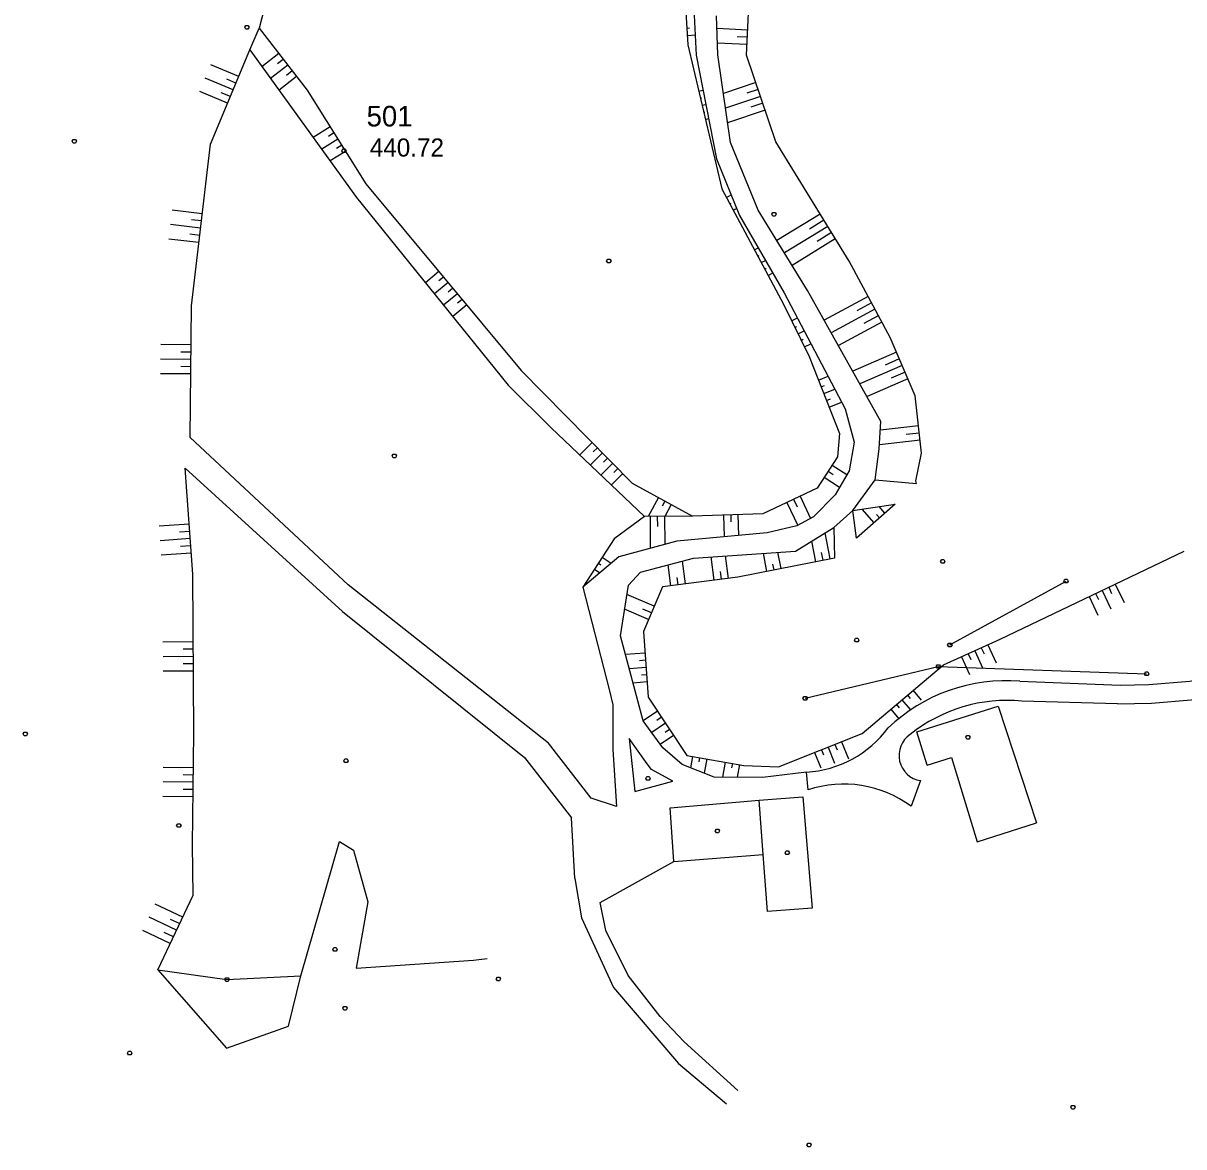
# Model space of a CAD drawing. Extents: x -664960 to -662754, y -993849 to -991145.
# Drawn here: x -664960.2 to -664768.3, y -993629.6 to -993443.9 of the extents above; entities that cross this region are included whole.
import ezdxf

# ---------------------------------------------------------------- set-up
doc = ezdxf.new("R2010")
doc.units = 0
for name, color, linetype in [('Vrstva 1', 7, 'Continuous'), ('Vrstva 11', 7, 'Continuous'), ('Vrstva 13', 7, 'Continuous'), ('Vrstva 18', 7, 'Continuous'), ('Vrstva 23', 7, 'Continuous'), ('Vrstva 27', 7, 'Continuous'), ('Vrstva 37', 7, 'Continuous'), ('Vrstva 57', 7, 'Continuous'), ('Vrstva 63', 7, 'Continuous'), ('Vrstva 8', 7, 'Continuous'), ('Vrstva 9', 7, 'Continuous')]:
    doc.layers.add(name, color=color, linetype=linetype)

msp = doc.modelspace()

# ---------------------------------------------------------------- linework, layer by layer
at = {"layer": 'Vrstva 11'}
for p, q in [((-664802.496, -993579.204), (-664792.708, -993576.061)), ((-664852.637, -993582.457), (-664837.866, -993581.285)), ((-664829.764, -993590.158), (-664837.168, -993590.719))]:
    msp.add_line(p, q, dxfattribs=at)
for points in [[(-664810.763, -993566.551), (-664812.455, -993561.016), (-664798.999, -993556.803), (-664792.708, -993576.061)], [(-664810.763, -993566.551), (-664806.76, -993565.249), (-664802.496, -993579.204)], [(-664837.168, -993590.719), (-664837.866, -993581.285), (-664838.53, -993572.31), (-664831.29, -993571.79), (-664829.764, -993590.158)], [(-664852.637, -993582.457), (-664853.24, -993573.56), (-664838.53, -993572.31)]]:
    msp.add_lwpolyline(points, dxfattribs=at)
at = {"layer": 'Vrstva 13'}
for points in [[(-664951.534, -993463.13), (-664951.354, -993463.43), (-664951.534, -993463.73), (-664951.894, -993463.73), (-664952.074, -993463.43), (-664951.894, -993463.13), (-664951.534, -993463.13)], [(-664835.885, -993475.193), (-664835.705, -993475.493), (-664835.885, -993475.793), (-664836.245, -993475.793), (-664836.425, -993475.493), (-664836.245, -993475.193), (-664835.885, -993475.193)], [(-664863.186, -993482.897), (-664863.006, -993483.197), (-664863.186, -993483.497), (-664863.546, -993483.497), (-664863.726, -993483.197), (-664863.546, -993482.897), (-664863.186, -993482.897)], [(-664898.628, -993515.117), (-664898.448, -993515.417), (-664898.628, -993515.717), (-664898.988, -993515.717), (-664899.168, -993515.417), (-664898.988, -993515.117), (-664898.628, -993515.117)], [(-664822.219, -993545.565), (-664822.039, -993545.865), (-664822.219, -993546.165), (-664822.579, -993546.165), (-664822.759, -993545.865), (-664822.579, -993545.565), (-664822.219, -993545.565)], [(-664959.61, -993561.068), (-664959.43, -993561.368), (-664959.61, -993561.668), (-664959.97, -993561.668), (-664960.15, -993561.368), (-664959.97, -993561.068), (-664959.61, -993561.068)], [(-664906.634, -993565.503), (-664906.454, -993565.803), (-664906.634, -993566.103), (-664906.994, -993566.103), (-664907.174, -993565.803), (-664906.994, -993565.503), (-664906.634, -993565.503)], [(-664908.433, -993596.677), (-664908.253, -993596.977), (-664908.433, -993597.277), (-664908.793, -993597.277), (-664908.973, -993596.977), (-664908.793, -993596.677), (-664908.433, -993596.677)]]:
    msp.add_lwpolyline(points, dxfattribs=at)
at = {"layer": 'Vrstva 18'}
for points in [[(-664923.01, -993444.3), (-664922.83, -993444.6), (-664923.01, -993444.9), (-664923.37, -993444.9), (-664923.55, -993444.6), (-664923.37, -993444.3), (-664923.01, -993444.3)], [(-664934.25, -993576.2), (-664934.07, -993576.5), (-664934.25, -993576.8), (-664934.61, -993576.8), (-664934.79, -993576.5), (-664934.61, -993576.2), (-664934.25, -993576.2)], [(-664881.433, -993601.55), (-664881.253, -993601.85), (-664881.433, -993602.15), (-664881.793, -993602.15), (-664881.973, -993601.85), (-664881.793, -993601.55), (-664881.433, -993601.55)], [(-664906.79, -993606.41), (-664906.61, -993606.71), (-664906.79, -993607.01), (-664907.15, -993607.01), (-664907.33, -993606.71), (-664907.15, -993606.41), (-664906.79, -993606.41)], [(-664942.38, -993613.82), (-664942.2, -993614.12), (-664942.38, -993614.42), (-664942.74, -993614.42), (-664942.92, -993614.12), (-664942.74, -993613.82), (-664942.38, -993613.82)], [(-664786.468, -993622.755), (-664786.288, -993623.055), (-664786.468, -993623.355), (-664786.828, -993623.355), (-664787.008, -993623.055), (-664786.828, -993622.755), (-664786.468, -993622.755)], [(-664830.086, -993628.994), (-664829.906, -993629.294), (-664830.086, -993629.594), (-664830.446, -993629.594), (-664830.626, -993629.294), (-664830.446, -993628.994), (-664830.086, -993628.994)]]:
    msp.add_lwpolyline(points, dxfattribs=at)
at = {"layer": 'Vrstva 23'}
for p, q in [((-664795.421, -993552.658), (-664778.865, -993553.318)), ((-664779.297, -993556.373), (-664795.089, -993555.953)), ((-664830.44, -993570.63), (-664830.71, -993567.69)), ((-664811.85, -993569.09), (-664813.41, -993573.33))]:
    msp.add_line(p, q, dxfattribs=at)
for points in [[(-664778.865, -993553.318), (-664774.13, -993553.174), (-664767.338, -993552.644), (-664762.115, -993551.613)], [(-664779.297, -993556.373), (-664773.686, -993556.3), (-664767.101, -993555.71), (-664761.262, -993554.563)]]:
    msp.add_lwpolyline(points, dxfattribs=at)
for centre, radius, start, end in [((-664797.685, -993580.909), 28.342, 85.41758, 133.50928), ((-664797.554, -993581.435), 25.601, 84.47369, 128.66666), ((-664831.789, -993549.591), 18.131, 273.41191, 323.58536), ((-664811.201, -993564.935), 4.206, 123.95198, 261.12469), ((-664824.509, -993588.276), 18.616, 53.40247, 108.57972)]:
    msp.add_arc(centre, radius, start, end, dxfattribs=at)
at = {"layer": 'Vrstva 27'}
for p, q in [((-664868.995, -993585.253), (-664869.51, -993575.25)), ((-664864.802, -993589.247), (-664852.637, -993582.457))]:
    msp.add_line(p, q, dxfattribs=at)
for points in [[(-664849.24, -993442.58), (-664848.96, -993449.22), (-664845.6, -993466.32), (-664841.78, -993475.72), (-664834.37, -993488.49), (-664824.32, -993507.62), (-664822.82, -993513.13), (-664823.66, -993517.88), (-664825.98, -993521.88), (-664829.54, -993525.5), (-664832.27, -993526.99), (-664837.19, -993528.16), (-664852.12, -993529.5), (-664861.73, -993532.08), (-664867.68, -993537.12), (-664863.27, -993554.24), (-664862.7, -993556.56), (-664862.7, -993563.93)], [(-664830.71, -993567.69), (-664837.96, -993568.55), (-664845.98, -993568.5), (-664851.25, -993566.43), (-664854.46, -993563.69), (-664857.68, -993559.18), (-664861.44, -993545.16), (-664860.14, -993536.81), (-664858.11, -993534.64), (-664849.37, -993532.3), (-664832.51, -993531.15), (-664826.16, -993527.24), (-664823.02, -993524.47), (-664819.37, -993519.36), (-664818.69, -993514.28), (-664818.39, -993509.72), (-664830.53, -993488.08), (-664838.71, -993474.83), (-664843.26, -993463.66), (-664845.33, -993449.14), (-664845.56, -993442.68)], [(-664862.7, -993563.93), (-664862.1, -993573.36), (-664866.27, -993571.96), (-664873.33, -993562.89), (-664906.44, -993536.75), (-664932.56, -993512.4)], [(-664933.37, -993517.43), (-664907.41, -993541.16), (-664877.3, -993565.24), (-664869.51, -993575.25)], [(-664859.09, -993570.89), (-664852.77, -993569.15), (-664856.29, -993567.22), (-664857.02, -993566.29), (-664860.03, -993562.12), (-664859.09, -993570.89)], [(-664868.995, -993585.253), (-664867.883, -993591.761), (-664862.613, -993603.257)], [(-664842.027, -993620.315), (-664850.896, -993612.253), (-664854.891, -993608.062), (-664860.192, -993601.276), (-664863.867, -993593.843), (-664864.802, -993589.247)], [(-664862.613, -993603.257), (-664851.845, -993615.834), (-664843.931, -993622.494)]]:
    msp.add_lwpolyline(points, dxfattribs=at)
at = {"layer": 'Vrstva 37'}
for points in [[(-664808.74, -993549.927), (-664808.56, -993550.227), (-664808.74, -993550.527), (-664809.1, -993550.527), (-664809.28, -993550.227), (-664809.1, -993549.927), (-664808.74, -993549.927)], [(-664774.309, -993551.112), (-664774.129, -993551.412), (-664774.309, -993551.712), (-664774.669, -993551.712), (-664774.849, -993551.412), (-664774.669, -993551.112), (-664774.309, -993551.112)], [(-664830.74, -993555.18), (-664830.56, -993555.48), (-664830.74, -993555.78), (-664831.1, -993555.78), (-664831.28, -993555.48), (-664831.1, -993555.18), (-664830.74, -993555.18)]]:
    msp.add_lwpolyline(points, dxfattribs=at)
at = {"layer": 'Vrstva 57'}
msp.add_lwpolyline([(-664830.92, -993555.48), (-664808.92, -993550.227), (-664774.489, -993551.412)], dxfattribs=at)
at = {"layer": 'Vrstva 63'}
for p, q in [((-664850.473, -993444.739), (-664850.033, -993444.71)), ((-664840.428, -993445.053), (-664845.484, -993444.818)), ((-664850.393, -993445.936), (-664849.102, -993445.851)), ((-664840.539, -993447.45), (-664845.398, -993447.224)), ((-664840.483, -993446.251), (-664842.134, -993446.175)), ((-664917.894, -993448.947), (-664920.693, -993451.109)), ((-664924.523, -993452.717), (-664929.139, -993450.794)), ((-664916.427, -993450.846), (-664919.285, -993453.054)), ((-664917.161, -993449.896), (-664918.102, -993450.624)), ((-664925.446, -993454.932), (-664930.062, -993453.01)), ((-664924.985, -993453.824), (-664926.522, -993453.184)), ((-664914.959, -993452.745), (-664917.876, -993454.998)), ((-664915.693, -993451.795), (-664916.654, -993452.538)), ((-664848.499, -993455.136), (-664847.829, -993454.978)), ((-664839.088, -993453.733), (-664844.419, -993455.531)), ((-664838.704, -993454.87), (-664840.55, -993455.493)), ((-664926.369, -993457.148), (-664930.984, -993455.225)), ((-664925.907, -993456.04), (-664927.444, -993455.4)), ((-664848.225, -993456.304), (-664848.016, -993456.255)), ((-664838.321, -993456.007), (-664844.074, -993457.948)), ((-664847.951, -993457.472), (-664847.365, -993457.335)), ((-664847.677, -993458.641), (-664847.496, -993458.598)), ((-664837.554, -993458.282), (-664843.73, -993460.365)), ((-664837.937, -993457.144), (-664839.923, -993457.814)), ((-664847.403, -993459.809), (-664846.902, -993459.691)), ((-664909.434, -993461.035), (-664912.23, -993462.79)), ((-664908.796, -993462.052), (-664909.704, -993462.622)), ((-664908.158, -993463.068), (-664910.819, -993464.738)), ((-664907.52, -993464.084), (-664908.384, -993464.626)), ((-664906.882, -993465.101), (-664909.408, -993466.686)), ((-664843.945, -993472.717), (-664843.169, -993472.302)), ((-664843.377, -993473.775), (-664843.157, -993473.657)), ((-664930.549, -993475.41), (-664935.514, -993474.823)), ((-664842.81, -993474.833), (-664842.26, -993474.538)), ((-664828.457, -993475.451), (-664835.611, -993479.849)), ((-664930.831, -993477.793), (-664935.796, -993477.206)), ((-664930.69, -993476.602), (-664932.343, -993476.406)), ((-664827.2, -993477.495), (-664834.351, -993481.891)), ((-664827.829, -993476.473), (-664830.21, -993477.937)), ((-664931.113, -993480.177), (-664936.078, -993479.59)), ((-664930.972, -993478.985), (-664932.625, -993478.789)), ((-664825.943, -993479.54), (-664833.09, -993483.934)), ((-664826.572, -993478.518), (-664828.952, -993479.981)), ((-664839.305, -993481.37), (-664838.692, -993481.042)), ((-664838.738, -993482.428), (-664838.522, -993482.312)), ((-664838.17, -993483.485), (-664837.487, -993483.119)), ((-664891.461, -993484.949), (-664893.68, -993486.796)), ((-664837.603, -993484.543), (-664837.364, -993484.414)), ((-664837.036, -993485.6), (-664836.282, -993485.196)), ((-664889.926, -993486.793), (-664892.173, -993488.664)), ((-664890.693, -993485.871), (-664891.437, -993486.49)), ((-664889.158, -993487.715), (-664889.911, -993488.342)), ((-664888.39, -993488.637), (-664890.666, -993490.532)), ((-664887.622, -993489.56), (-664888.385, -993490.195)), ((-664820.531, -993489.083), (-664827.784, -993492.975)), ((-664886.854, -993490.482), (-664889.159, -993492.401)), ((-664819.396, -993491.198), (-664826.61, -993495.068)), ((-664819.964, -993490.141), (-664822.372, -993491.433)), ((-664833.152, -993493.095), (-664832.196, -993492.629)), ((-664818.262, -993493.313), (-664825.435, -993497.162)), ((-664818.829, -993492.256), (-664821.225, -993493.541)), ((-664832.627, -993494.174), (-664832.297, -993494.014)), ((-664832.101, -993495.253), (-664831.079, -993494.755)), ((-664932.412, -993497.083), (-664937.412, -993497.035)), ((-664831.575, -993496.332), (-664831.224, -993496.16)), ((-664831.05, -993497.41), (-664829.962, -993496.88)), ((-664932.424, -993498.283), (-664934.089, -993498.267)), ((-664815.841, -993498.285), (-664823.049, -993501.415)), ((-664932.435, -993499.483), (-664937.435, -993499.435)), ((-664932.447, -993500.683), (-664934.112, -993500.667)), ((-664814.885, -993500.486), (-664821.869, -993503.519)), ((-664815.363, -993499.385), (-664817.726, -993500.412)), ((-664932.459, -993501.883), (-664937.458, -993501.835)), ((-664828.73, -993502.894), (-664827.135, -993502.262)), ((-664813.929, -993502.687), (-664820.688, -993505.623)), ((-664814.407, -993501.587), (-664816.695, -993502.581)), ((-664828.287, -993504.01), (-664827.717, -993503.784)), ((-664827.845, -993505.125), (-664826.012, -993504.399)), ((-664827.403, -993506.241), (-664826.753, -993505.983)), ((-664826.96, -993507.356), (-664824.89, -993506.535)), ((-664812.171, -993510.451), (-664818.484, -993511.147)), ((-664812.039, -993511.643), (-664814.212, -993511.883)), ((-664866.096, -993513.227), (-664868.189, -993515.289)), ((-664865.254, -993514.081), (-664865.941, -993514.759)), ((-664811.908, -993512.836), (-664818.644, -993513.579)), ((-664864.411, -993514.936), (-664866.447, -993516.942)), ((-664863.569, -993515.791), (-664864.237, -993516.449)), ((-664862.727, -993516.645), (-664864.705, -993518.595)), ((-664861.042, -993518.355), (-664862.963, -993520.247)), ((-664861.885, -993517.5), (-664862.534, -993518.14)), ((-664827.101, -993517.936), (-664826.277, -993518.473)), ((-664826.446, -993516.931), (-664824.024, -993518.508)), ((-664827.756, -993518.942), (-664825.23, -993520.587)), ((-664831.77, -993522.078), (-664830.027, -993525.766)), ((-664855.157, -993522.306), (-664856.873, -993525.435)), ((-664854.105, -993522.883), (-664854.569, -993523.729)), ((-664853.053, -993523.459), (-664854.125, -993525.415)), ((-664833.94, -993523.103), (-664832.137, -993526.917)), ((-664832.855, -993522.591), (-664832.265, -993523.84)), ((-664817.73, -993524.879), (-664818.692, -993523.794)), ((-664856.555, -993525.433), (-664856.516, -993530.68)), ((-664855.355, -993525.424), (-664855.343, -993527.067)), ((-664854.155, -993525.415), (-664854.12, -993530.037)), ((-664844.426, -993525.208), (-664844.305, -993528.799)), ((-664843.226, -993525.168), (-664843.187, -993526.341)), ((-664842.027, -993525.128), (-664841.911, -993528.584)), ((-664819.525, -993526.471), (-664821.509, -993524.234)), ((-664818.627, -993525.675), (-664819.118, -993525.122)), ((-664932.72, -993526.696), (-664937.708, -993527.046)), ((-664932.636, -993527.893), (-664934.297, -993528.009)), ((-664932.552, -993529.09), (-664937.54, -993529.44)), ((-664829.149, -993532.91), (-664829.823, -993529.496)), ((-664826.794, -993532.445), (-664827.642, -993528.153)), ((-664932.384, -993531.484), (-664937.372, -993531.834)), ((-664932.468, -993530.287), (-664934.129, -993530.403)), ((-664837.235, -993534.507), (-664837.827, -993531.513)), ((-664834.881, -993534.042), (-664835.413, -993531.348)), ((-664827.972, -993532.678), (-664828.225, -993531.394)), ((-664865.097, -993533.162), (-664864.704, -993533.418)), ((-664864.442, -993532.157), (-664862.961, -993533.123)), ((-664853.102, -993536.899), (-664853.556, -993533.421)), ((-664850.722, -993536.589), (-664851.217, -993532.794)), ((-664845.958, -993535.968), (-664846.462, -993532.102)), ((-664843.578, -993535.658), (-664844.063, -993531.938)), ((-664836.058, -993534.275), (-664836.245, -993533.327)), ((-664865.753, -993534.167), (-664864.872, -993534.741)), ((-664851.912, -993536.744), (-664852.07, -993535.533)), ((-664844.768, -993535.813), (-664844.933, -993534.55)), ((-664807.01, -993546.65), (-664787.8, -993536.1)), ((-664780.762, -993537.129), (-664780.277, -993538.142)), ((-664779.679, -993536.611), (-664778.224, -993539.652)), ((-664855.866, -993540.271), (-664860.376, -993538.326)), ((-664784.009, -993538.684), (-664782.554, -993541.723)), ((-664782.927, -993538.166), (-664782.442, -993539.178)), ((-664781.844, -993537.648), (-664780.389, -993540.688)), ((-664856.817, -993542.475), (-664860.757, -993540.776)), ((-664856.342, -993541.373), (-664857.749, -993540.766)), ((-664932.059, -993546.176), (-664937.059, -993546.213)), ((-664801.811, -993547.121), (-664801.365, -993548.108)), ((-664800.717, -993546.626), (-664799.372, -993549.602)), ((-664932.041, -993548.576), (-664937.041, -993548.612)), ((-664932.05, -993547.376), (-664933.715, -993547.388)), ((-664857.394, -993547.995), (-664860.615, -993548.236)), ((-664805.091, -993548.604), (-664803.768, -993551.532)), ((-664803.998, -993548.109), (-664803.555, -993549.088)), ((-664802.904, -993547.615), (-664801.57, -993550.567)), ((-664932.024, -993550.976), (-664937.024, -993551.012)), ((-664932.033, -993549.776), (-664933.698, -993549.788)), ((-664857.215, -993550.388), (-664859.982, -993550.595)), ((-664857.305, -993549.192), (-664858.302, -993549.266)), ((-664857.037, -993552.782), (-664859.35, -993552.954)), ((-664857.126, -993551.585), (-664857.972, -993551.648)), ((-664813.09, -993554.19), (-664811.76, -993555.765)), ((-664815.84, -993556.513), (-664815.396, -993557.038)), ((-664814.924, -993555.739), (-664813.592, -993557.316)), ((-664814.007, -993554.964), (-664813.563, -993555.489)), ((-664855.308, -993557.608), (-664857.68, -993559.18)), ((-664854.645, -993558.609), (-664855.423, -993559.124)), ((-664816.757, -993557.287), (-664815.423, -993558.866)), ((-664853.982, -993559.609), (-664856.285, -993561.134)), ((-664853.319, -993560.609), (-664854.074, -993561.11)), ((-664852.656, -993561.61), (-664854.889, -993563.089)), ((-664829.356, -993564.423), (-664828.355, -993566.944)), ((-664828.241, -993563.98), (-664827.897, -993564.846)), ((-664827.126, -993563.537), (-664826.061, -993566.217)), ((-664826.01, -993563.094), (-664825.645, -993564.013)), ((-664824.895, -993562.651), (-664823.767, -993565.491)), ((-664849.554, -993565.071), (-664849.888, -993566.965)), ((-664848.372, -993565.28), (-664848.497, -993565.99)), ((-664847.19, -993565.488), (-664847.608, -993567.86)), ((-664844.132, -993566.027), (-664844.569, -993568.509)), ((-664842.95, -993566.235), (-664843.084, -993566.995)), ((-664932.012, -993566.962), (-664937.012, -993566.908)), ((-664932.025, -993568.162), (-664933.69, -993568.144)), ((-664841.768, -993566.443), (-664842.135, -993568.524)), ((-664932.038, -993569.362), (-664937.038, -993569.308)), ((-664932.064, -993571.762), (-664937.064, -993571.708)), ((-664932.051, -993570.562), (-664933.716, -993570.544)), ((-664933.795, -993591.632), (-664938.318, -993589.502)), ((-664934.817, -993593.803), (-664939.341, -993591.674)), ((-664934.306, -993592.718), (-664935.812, -993592.009)), ((-664935.839, -993595.975), (-664940.363, -993593.845)), ((-664935.328, -993594.889), (-664936.835, -993594.18))]:
    msp.add_line(p, q, dxfattribs=at)
for points in [[(-664898.59, -993333.26), (-664902.31, -993350.2), (-664909.16, -993368.82), (-664909.77, -993375.53), (-664911.87, -993405.23), (-664914.94, -993420.64), (-664921.16, -993444.72)], [(-664859.38, -993364.18), (-664849.21, -993374.21), (-664846.88, -993380.73), (-664848.42, -993405.79), (-664850.27, -993424.55), (-664850.47, -993432.34), (-664850.71, -993441.15), (-664850.29, -993447.5), (-664844.71, -993471.29), (-664834.5, -993490.33), (-664830.27, -993499.01), (-664825.23, -993511.72), (-664825.56, -993515.57), (-664828.92, -993520.73), (-664837.93, -993524.99), (-664849.55, -993525.38), (-664857.49, -993525.44), (-664862.48, -993529.15), (-664867.68, -993537.12)], [(-664819.37, -993519.36), (-664812.5, -993519.97), (-664812.63, -993519.54), (-664811.67, -993514.99), (-664812.72, -993505.47), (-664816.89, -993495.87), (-664823.65, -993483.27), (-664835.78, -993463.54), (-664840.62, -993449.19), (-664839.43, -993423.59), (-664840.03, -993402.16), (-664837.64, -993378.42), (-664841.52, -993376.89)], [(-664932.56, -993512.4), (-664932.35, -993490.64), (-664929.19, -993463.92), (-664922.7, -993448.34), (-664921.16, -993444.72)], [(-664921.16, -993444.72), (-664913.24, -993454.97), (-664903.5, -993470.49), (-664877.83, -993501.32), (-664859.49, -993519.93), (-664849.55, -993525.38)], [(-664922.7, -993448.34), (-664905.05, -993472.7), (-664880.02, -993503.73), (-664872.92, -993510.8), (-664857.49, -993525.44)], [(-664937.89, -993600.33), (-664932.08, -993587.99), (-664932.15, -993579.68), (-664931.95, -993561.2), (-664932.14, -993534.97), (-664933.37, -993517.43)], [(-664822.41, -993529.03), (-664823.02, -993524.47), (-664816.04, -993523.38), (-664822.41, -993529.03)], [(-664826.16, -993527.24), (-664826.06, -993532.3), (-664842.06, -993535.46), (-664854.49, -993537.08), (-664857.66, -993544.43), (-664856.85, -993555.28), (-664850.47, -993564.91), (-664841.05, -993566.57), (-664835.34, -993566.8), (-664821.52, -993561.31), (-664808.07, -993549.95), (-664798.69, -993545.71), (-664768.31, -993531.17)], [(-664808, -993532.56), (-664807.82, -993532.86), (-664808, -993533.16), (-664808.36, -993533.16), (-664808.54, -993532.86), (-664808.36, -993532.56), (-664808, -993532.56)], [(-664787.62, -993535.8), (-664787.44, -993536.1), (-664787.62, -993536.4), (-664787.98, -993536.4), (-664788.16, -993536.1), (-664787.98, -993535.8), (-664787.62, -993535.8)], [(-664806.83, -993546.35), (-664806.65, -993546.65), (-664806.83, -993546.95), (-664807.19, -993546.95), (-664807.37, -993546.65), (-664807.19, -993546.35), (-664806.83, -993546.35)], [(-664856.71, -993568.43), (-664856.53, -993568.73), (-664856.71, -993569.03), (-664857.07, -993569.03), (-664857.25, -993568.73), (-664857.07, -993568.43), (-664856.71, -993568.43)], [(-664937.89, -993600.33), (-664926.58, -993613.29), (-664916.32, -993609.64), (-664914.26, -993601.34), (-664907.86, -993579.12), (-664905.54, -993580.57), (-664903.18, -993589.1), (-664905.1, -993600.06), (-664885.76, -993598.78), (-664883.49, -993598.49)], [(-664937.89, -993600.33), (-664926.48, -993601.96), (-664914.26, -993601.34)], [(-664926.3, -993601.66), (-664926.12, -993601.96), (-664926.3, -993602.26), (-664926.66, -993602.26), (-664926.84, -993601.96), (-664926.66, -993601.66), (-664926.3, -993601.66)]]:
    msp.add_lwpolyline(points, dxfattribs=at)
at = {"layer": 'Vrstva 8'}
msp.add_lwpolyline([(-664906.96, -993464.69), (-664906.78, -993464.99), (-664906.96, -993465.29), (-664907.32, -993465.29), (-664907.5, -993464.99), (-664907.32, -993464.69), (-664906.96, -993464.69)], dxfattribs=at)
at = {"layer": 'Vrstva 9'}
for points in [[(-664803.852, -993561.611), (-664803.672, -993561.911), (-664803.852, -993562.211), (-664804.212, -993562.211), (-664804.392, -993561.911), (-664804.212, -993561.611), (-664803.852, -993561.611)], [(-664845.238, -993577.092), (-664845.058, -993577.392), (-664845.238, -993577.692), (-664845.598, -993577.692), (-664845.778, -993577.392), (-664845.598, -993577.092), (-664845.238, -993577.092)], [(-664833.708, -993580.697), (-664833.528, -993580.997), (-664833.708, -993581.297), (-664834.068, -993581.297), (-664834.248, -993580.997), (-664834.068, -993580.697), (-664833.708, -993580.697)]]:
    msp.add_lwpolyline(points, dxfattribs=at)

# ---------------------------------------------------------------- texts
at = {"layer": 'Vrstva 1'}
msp.add_text('501', height=3.4, dxfattribs=at).set_placement((-664903.398, -993460.982))
at = {"layer": 'Vrstva 63'}
msp.add_text('440.72', height=3, dxfattribs=at).set_placement((-664902.874, -993465.962))

doc.saveas('drawing.dxf')
